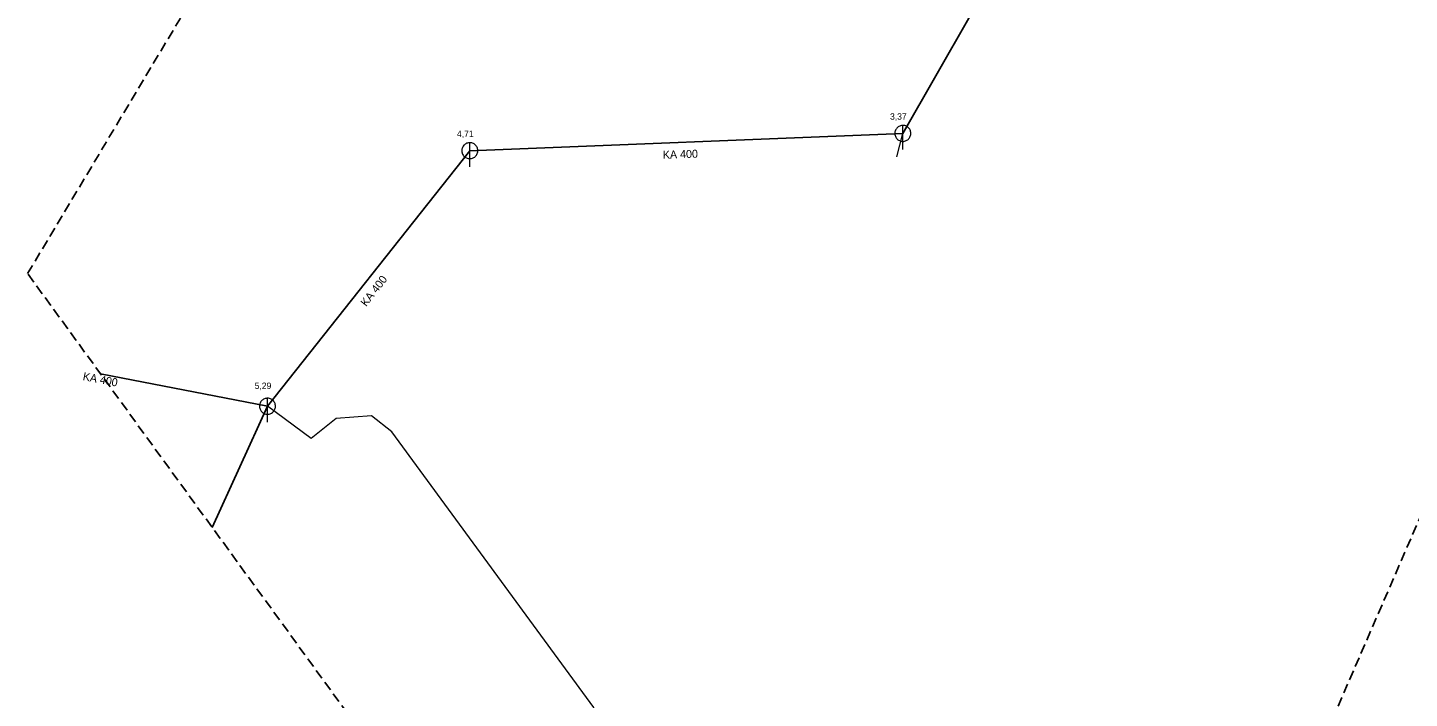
# Model space of a CAD drawing. Extents: x -724358 to -723714, y -973310 to -972026.
# Drawn here: x -724358.4 to -724185.8, y -973201.5 to -973117.7 of the extents above; entities that cross this region are included whole.
import ezdxf

# ---------------------------------------------------------------- set-up
doc = ezdxf.new("R2010")
doc.units = 0
doc.header["$LTSCALE"] = 0.4
doc.linetypes.add('MEDIUM_DASHED', pattern=[4.5, 3, -1.5])
for name, color, linetype, lineweight in [('1', 7, 'Continuous', 13), ('11', 7, 'Continuous', 13), ('14', 7, 'Continuous', 13), ('22', 7, 'Continuous', 13)]:
    doc.layers.add(name, color=color, linetype=linetype, lineweight=lineweight)

msp = doc.modelspace()

# ---------------------------------------------------------------- linework, layer by layer
at = {"layer": '1', "linetype": 'MEDIUM_DASHED', "lineweight": 25}
msp.add_lwpolyline([(-723809.944, -972026.35), (-723713.647, -972034.723), (-723734.581, -972361.295), (-724123.956, -973039.561), (-724241.187, -973309.611), (-724358.418, -973148.418), (-723860.186, -972315.24)], close=True, dxfattribs=at)
at = {"layer": '11'}
msp.add_line((-724249.827, -973133.824), (-724249.059, -973130.899), dxfattribs=at)
msp.add_lwpolyline([(-724256.51, -973283.709), (-724257.639, -973286.989), (-724289.277, -973243.486), (-724282.809, -973218.84), (-724286.02, -973211.489), (-724288.62, -973206.05), (-724287.949, -973204.649), (-724287.69, -973202.64), (-724312.92, -973168.17), (-724315.44, -973166.19), (-724319.85, -973166.51), (-724322.98, -973169.03), (-724328.449, -973164.989)], dxfattribs=at)
at = {"layer": '14', "lineweight": 25}
for p, q in [((-724328.449, -973164.989), (-724303.17, -973133.059)), ((-724349.297, -973160.959), (-724328.449, -973164.989)), ((-724335.345, -973180.143), (-724328.449, -973164.989))]:
    msp.add_line(p, q, dxfattribs=at)
msp.add_lwpolyline([(-724303.17, -973133.059), (-724249.059, -973130.899), (-724223.989, -973087.05)], dxfattribs=at)
at = {"layer": '22'}
for p, q in [((-724249.059, -973132.899), (-724249.058, -973129.899)), ((-724303.17, -973135.059), (-724303.169, -973132.059)), ((-724328.449, -973166.989), (-724328.448, -973163.989))]:
    msp.add_line(p, q, dxfattribs=at)
for points in [[(-724248.059, -973130.899), (-724248.064, -973130.79), (-724248.082, -973130.682), (-724248.112, -973130.576), (-724248.152, -973130.475), (-724248.204, -973130.378), (-724248.266, -973130.288), (-724248.338, -973130.205), (-724248.418, -973130.131), (-724248.506, -973130.065), (-724248.6, -973130.01), (-724248.7, -973129.965), (-724248.805, -973129.932), (-724248.912, -973129.91), (-724249.021, -973129.9), (-724249.131, -973129.902), (-724249.239, -973129.916), (-724249.346, -973129.941), (-724249.449, -973129.978), (-724249.547, -973130.027), (-724249.639, -973130.085), (-724249.725, -973130.154), (-724249.802, -973130.231), (-724249.871, -973130.317), (-724249.93, -973130.409), (-724249.978, -973130.507), (-724250.015, -973130.61), (-724250.041, -973130.717), (-724250.055, -973130.825), (-724250.058, -973130.935), (-724250.048, -973131.044), (-724250.027, -973131.151), (-724249.993, -973131.255), (-724249.949, -973131.355), (-724249.894, -973131.45), (-724249.828, -973131.538), (-724249.754, -973131.618), (-724249.671, -973131.69), (-724249.581, -973131.752), (-724249.485, -973131.804), (-724249.383, -973131.845), (-724249.278, -973131.875), (-724249.17, -973131.893), (-724249.06, -973131.899), (-724248.951, -973131.893), (-724248.843, -973131.875), (-724248.738, -973131.846), (-724248.636, -973131.805), (-724248.539, -973131.753), (-724248.449, -973131.691), (-724248.366, -973131.62), (-724248.291, -973131.54), (-724248.226, -973131.452), (-724248.17, -973131.358), (-724248.126, -973131.258), (-724248.092, -973131.154), (-724248.07, -973131.046), (-724248.06, -973130.937)], [(-724302.17, -973133.059), (-724302.175, -973132.95), (-724302.193, -973132.842), (-724302.223, -973132.736), (-724302.263, -973132.635), (-724302.315, -973132.538), (-724302.377, -973132.448), (-724302.449, -973132.365), (-724302.529, -973132.291), (-724302.617, -973132.225), (-724302.711, -973132.17), (-724302.811, -973132.125), (-724302.916, -973132.092), (-724303.023, -973132.07), (-724303.132, -973132.06), (-724303.242, -973132.062), (-724303.35, -973132.076), (-724303.457, -973132.101), (-724303.56, -973132.138), (-724303.658, -973132.187), (-724303.75, -973132.245), (-724303.836, -973132.314), (-724303.913, -973132.391), (-724303.982, -973132.477), (-724304.041, -973132.569), (-724304.089, -973132.667), (-724304.126, -973132.77), (-724304.152, -973132.877), (-724304.166, -973132.985), (-724304.169, -973133.095), (-724304.159, -973133.204), (-724304.138, -973133.311), (-724304.104, -973133.415), (-724304.06, -973133.515), (-724304.005, -973133.61), (-724303.939, -973133.698), (-724303.865, -973133.778), (-724303.782, -973133.85), (-724303.692, -973133.912), (-724303.596, -973133.964), (-724303.494, -973134.005), (-724303.389, -973134.035), (-724303.281, -973134.053), (-724303.171, -973134.059), (-724303.062, -973134.053), (-724302.954, -973134.035), (-724302.849, -973134.006), (-724302.747, -973133.965), (-724302.65, -973133.913), (-724302.56, -973133.851), (-724302.477, -973133.78), (-724302.402, -973133.7), (-724302.337, -973133.612), (-724302.281, -973133.518), (-724302.237, -973133.418), (-724302.203, -973133.314), (-724302.181, -973133.206), (-724302.171, -973133.097)], [(-724327.449, -973164.989), (-724327.454, -973164.88), (-724327.472, -973164.772), (-724327.502, -973164.666), (-724327.542, -973164.565), (-724327.594, -973164.468), (-724327.656, -973164.378), (-724327.728, -973164.295), (-724327.808, -973164.221), (-724327.896, -973164.155), (-724327.99, -973164.1), (-724328.09, -973164.055), (-724328.195, -973164.022), (-724328.302, -973164), (-724328.411, -973163.99), (-724328.521, -973163.992), (-724328.629, -973164.006), (-724328.736, -973164.031), (-724328.839, -973164.068), (-724328.937, -973164.117), (-724329.029, -973164.175), (-724329.115, -973164.244), (-724329.192, -973164.321), (-724329.261, -973164.407), (-724329.32, -973164.499), (-724329.368, -973164.597), (-724329.405, -973164.7), (-724329.431, -973164.807), (-724329.445, -973164.915), (-724329.448, -973165.025), (-724329.438, -973165.134), (-724329.417, -973165.241), (-724329.383, -973165.345), (-724329.339, -973165.445), (-724329.284, -973165.54), (-724329.218, -973165.628), (-724329.144, -973165.708), (-724329.061, -973165.78), (-724328.971, -973165.842), (-724328.875, -973165.894), (-724328.773, -973165.935), (-724328.668, -973165.965), (-724328.56, -973165.983), (-724328.45, -973165.989), (-724328.341, -973165.983), (-724328.233, -973165.965), (-724328.128, -973165.936), (-724328.026, -973165.895), (-724327.929, -973165.843), (-724327.839, -973165.781), (-724327.756, -973165.71), (-724327.681, -973165.63), (-724327.616, -973165.542), (-724327.56, -973165.448), (-724327.516, -973165.348), (-724327.482, -973165.244), (-724327.46, -973165.136), (-724327.45, -973165.027)]]:
    msp.add_lwpolyline(points, close=True, dxfattribs=at)

# ---------------------------------------------------------------- texts
at = {"layer": '1'}
for s, p in [('3,37', (-724250.66, -973129.188)), ('4,71', (-724304.769, -973131.348)), ('5,29', (-724330.049, -973162.837))]:
    msp.add_text(s, height=0.8, dxfattribs=at).set_placement(p)
for rotation, p in [(2, (-724279.032, -973134.083)), (52, (-724316.115, -973152.608)), (349, (-724351.579, -973161.709))]:
    msp.add_text('KA 400', height=1, rotation=rotation, dxfattribs=at).set_placement(p)

doc.saveas('drawing.dxf')
